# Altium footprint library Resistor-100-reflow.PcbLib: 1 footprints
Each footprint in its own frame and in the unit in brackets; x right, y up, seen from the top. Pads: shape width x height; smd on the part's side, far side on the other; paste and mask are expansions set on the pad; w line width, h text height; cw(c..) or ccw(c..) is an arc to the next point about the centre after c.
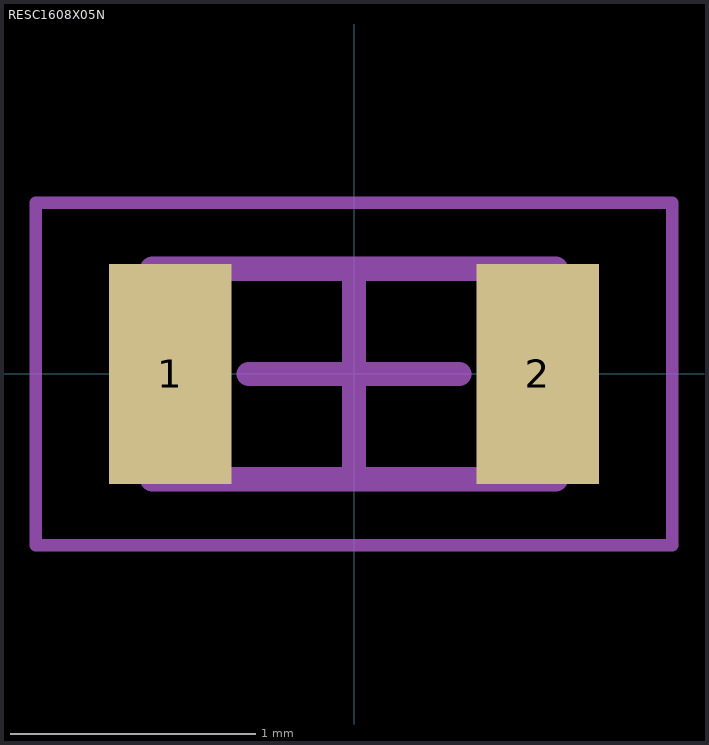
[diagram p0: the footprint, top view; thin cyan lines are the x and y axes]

## RESC1608X05N [mm] "Chip Resistor, 2-Leads, Body 1.58x0.85mm, IPC Medium Density"
height 0.5
pads (2):
  rect 0.5x0.9 smd: 1(-0.75,0) 2(0.75,0)
Mechanical 13:
  lines w0.1: -0.825,-0.43 0.825,-0.43 0.825,0.43 -0.825,0.43 -0.825,-0.43
Mechanical 15:
  lines w0.05: -1.3,-0.7 1.3,-0.7 1.3,0.7 -1.3,0.7 -1.3,-0.7
  lines w0.1: -0.43,0 0.43,0 ; 0,-0.43 0,0.43
3D body: height 0.5, standoff 0, extent 0.525,-0.43 0.825,0.43
3D body: height 0.5, standoff 0, extent -0.825,-0.43 -0.525,0.43
3D body: height 0.5, standoff 0, extent -0.525,-0.43 0.525,0.43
